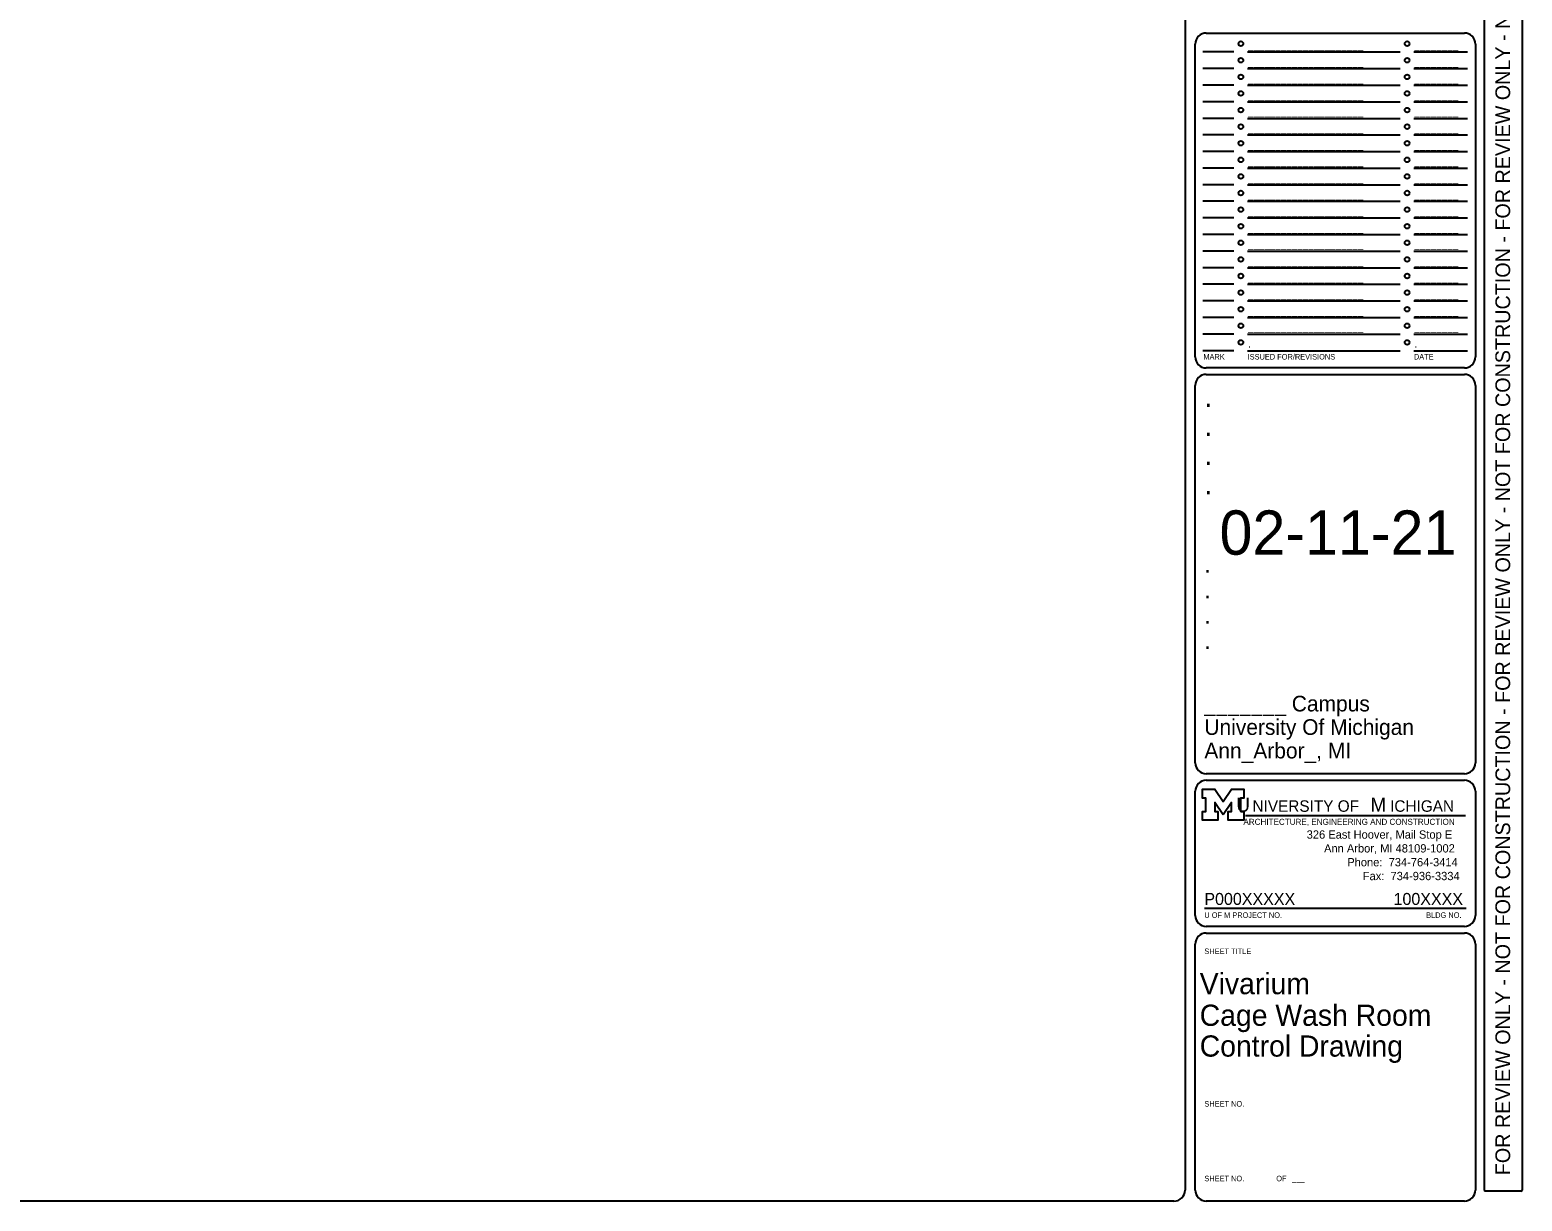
# Model space of a CAD drawing. Extents: x 0 to 567, y 1 to 184.
# Drawn here: x 432.3 to 567.1, y 1.7 to 107.6 of the extents above; entities that cross this region are included whole.
import ezdxf

# ---------------------------------------------------------------- set-up
doc = ezdxf.new("R2010")
doc.units = 0
for name, color, linetype in [('G-ANNO-CELL', 7, 'Continuous'), ('G-ANNO-LOGO', 7, 'Continuous'), ('G-ANNO-PROJ', 7, 'Continuous'), ('G-ANNO-TTLB', 7, 'Continuous'), ('G-TITL-TEXT', 7, 'Continuous')]:
    doc.layers.add(name, color=color, linetype=linetype)

msp = doc.modelspace()

# ---------------------------------------------------------------- linework, layer by layer
at = {"layer": 'G-ANNO-LOGO'}
for p, q in [((538.24, 38.17), (538.24, 38.96)), ((538.24, 38.96), (539.36, 38.96)), ((538.54, 38.17), (538.24, 38.17)), ((538.54, 36.95), (538.54, 38.17)), ((539.36, 38.96), (540.12, 37.86)), ((540.12, 37.86), (540.88, 38.96)), ((540.88, 38.96), (541.99, 38.96)), ((541.99, 38.17), (541.7, 38.17)), ((541.7, 38.17), (541.7, 36.98)), ((541.99, 38.96), (541.99, 38.17)), ((538.24, 36.16), (538.24, 36.95)), ((538.24, 36.95), (538.54, 36.95)), ((540.12, 36.66), (539.36, 37.76)), ((539.36, 37.76), (539.36, 36.95)), ((539.36, 36.95), (539.65, 36.95)), ((539.65, 36.95), (539.65, 36.16)), ((540.88, 37.76), (540.12, 36.66)), ((540.58, 36.16), (540.58, 36.95)), ((540.58, 36.95), (540.88, 36.95)), ((540.88, 36.95), (540.88, 37.76)), ((541.7, 36.98), (541.77, 36.95)), ((541.77, 36.95), (541.99, 36.95)), ((541.99, 36.95), (541.99, 36.16)), ((542.14, 36.59), (562.03, 36.59)), ((539.65, 36.16), (538.24, 36.16)), ((541.99, 36.16), (540.58, 36.16))]:
    msp.add_line(p, q, dxfattribs=at)
msp.add_lwpolyline([(540.12, 36.66), (539.36, 37.76), (539.36, 36.95), (539.65, 36.95), (539.65, 36.16), (538.24, 36.16), (538.24, 36.95), (538.54, 36.95), (538.54, 38.17), (538.24, 38.17), (538.24, 38.96), (539.36, 38.96), (540.12, 37.86), (540.88, 38.96), (541.99, 38.96), (541.99, 38.17), (541.7, 38.17), (541.7, 36.98), (541.77, 36.95), (541.99, 36.95), (541.99, 36.16), (540.58, 36.16), (540.58, 36.95), (540.88, 36.95), (540.88, 37.76)], close=True, dxfattribs=at)
at = {"layer": 'G-ANNO-TTLB'}
for p, q in [((541.08, 105.61), (538.29, 105.61)), ((542.33, 105.61), (556.11, 105.61)), ((557.36, 105.61), (562.2, 105.61)), ((541.08, 104.11), (538.29, 104.11)), ((542.33, 104.11), (556.11, 104.11)), ((557.36, 104.11), (562.2, 104.11)), ((541.08, 102.61), (538.29, 102.61)), ((542.33, 102.61), (556.11, 102.61)), ((557.36, 102.61), (562.2, 102.61)), ((541.08, 101.11), (538.29, 101.11)), ((542.33, 101.11), (556.11, 101.11)), ((557.36, 101.11), (562.2, 101.11)), ((541.08, 99.61), (538.29, 99.61)), ((542.33, 99.61), (556.11, 99.61)), ((557.36, 99.61), (562.2, 99.61)), ((541.08, 98.11), (538.29, 98.11)), ((542.33, 98.11), (556.11, 98.11)), ((557.36, 98.11), (562.2, 98.11)), ((541.08, 96.61), (538.29, 96.61)), ((542.33, 96.61), (556.11, 96.61)), ((557.36, 96.61), (562.2, 96.61)), ((541.08, 95.11), (538.29, 95.11)), ((542.33, 95.11), (556.11, 95.11)), ((557.36, 95.11), (562.2, 95.11)), ((541.08, 93.61), (538.29, 93.61)), ((542.33, 93.61), (556.11, 93.61)), ((557.36, 93.61), (562.2, 93.61)), ((541.08, 92.11), (538.29, 92.11)), ((542.33, 92.11), (556.11, 92.11)), ((557.36, 92.11), (562.2, 92.11)), ((541.08, 90.61), (538.29, 90.61)), ((542.33, 90.61), (556.11, 90.61)), ((557.36, 90.61), (562.2, 90.61)), ((541.08, 89.11), (538.29, 89.11)), ((542.33, 89.11), (556.11, 89.11)), ((557.36, 89.11), (562.2, 89.11)), ((541.08, 87.61), (538.29, 87.61)), ((542.33, 87.61), (556.11, 87.61)), ((557.36, 87.61), (562.2, 87.61)), ((541.08, 86.11), (538.29, 86.11)), ((542.33, 86.11), (556.11, 86.11)), ((557.36, 86.11), (562.2, 86.11)), ((541.08, 84.61), (538.29, 84.61)), ((542.33, 84.61), (556.11, 84.61)), ((557.36, 84.61), (562.2, 84.61)), ((541.08, 83.11), (538.29, 83.11)), ((542.33, 83.11), (556.11, 83.11)), ((557.36, 83.11), (562.2, 83.11)), ((541.08, 81.61), (538.29, 81.61)), ((542.33, 81.61), (556.11, 81.61)), ((557.36, 81.61), (562.2, 81.61)), ((541.08, 80.11), (538.29, 80.11)), ((542.33, 80.11), (556.11, 80.11)), ((557.36, 80.11), (562.2, 80.11)), ((541.08, 78.61), (538.29, 78.61)), ((542.33, 78.61), (556.11, 78.61)), ((557.36, 78.61), (562.2, 78.61)), ((562.09, 28.18), (538.42, 28.18))]:
    msp.add_line(p, q, dxfattribs=at)
for points in [[(536.67, 182.73), (536.67, 2.73)], [(563.73, 2.73), (563.73, 182.73)], [(567.15, 182.73), (567.15, 2.73)], [(538.59, 107.32), (561.92, 107.32)], [(537.59, 78.05), (537.59, 106.32)], [(562.92, 106.32), (562.92, 78.05)], [(561.92, 77.05), (538.59, 77.05)], [(538.59, 76.47), (561.92, 76.47)], [(537.59, 41.36), (537.59, 75.47)], [(562.92, 75.47), (562.92, 41.36)], [(561.92, 40.36), (538.59, 40.36)], [(538.59, 39.78), (561.92, 39.78)], [(537.59, 27.56), (537.59, 38.78)], [(562.92, 38.78), (562.92, 27.56)], [(561.92, 26.56), (538.59, 26.56)], [(538.59, 25.97), (561.92, 25.97)], [(537.59, 2.74), (537.59, 24.97)], [(562.92, 24.97), (562.92, 2.74)], [(535.67, 1.73), (291.92, 1.73)], [(561.92, 1.74), (538.59, 1.74)], [(567.06, 2.65), (563.81, 2.65)]]:
    msp.add_lwpolyline(points, dxfattribs=at)
for centre in [(541.72, 106.36), (556.75, 106.36), (541.72, 104.86), (556.75, 104.86), (541.72, 103.36), (556.75, 103.36), (541.72, 101.86), (556.75, 101.86), (541.72, 100.36), (556.75, 100.36), (541.72, 98.86), (556.75, 98.86), (541.72, 97.36), (556.75, 97.36), (541.72, 95.86), (556.75, 95.86), (541.72, 94.36), (556.75, 94.36), (541.72, 92.86), (556.75, 92.86), (541.72, 91.36), (556.75, 91.36), (541.72, 89.86), (556.75, 89.86), (541.72, 88.36), (556.75, 88.36), (541.72, 86.86), (556.75, 86.86), (541.72, 85.36), (556.75, 85.36), (541.72, 83.86), (556.75, 83.86), (541.72, 82.36), (556.75, 82.36), (541.72, 80.86), (556.75, 80.86), (541.72, 79.36), (556.75, 79.36)]:
    msp.add_circle(centre, 0.214, dxfattribs=at)
for centre, radius, start, end in [((538.59, 106.32), 1, 90.0001, 180.0001), ((561.92, 106.32), 1, 0.0001, 90.0001), ((538.59, 78.05), 1, 180, 270), ((561.92, 78.05), 1, 270, 360), ((538.59, 75.47), 1, 90, 180), ((561.92, 75.47), 1, 0, 90), ((538.59, 41.36), 1, 180, 270), ((561.92, 41.36), 1, 270, 0), ((538.59, 38.78), 1, 90, 180), ((561.92, 38.78), 1, 0, 90), ((538.59, 27.56), 1, 180, 270), ((561.92, 27.56), 1, 270, 360), ((538.59, 24.97), 1, 90, 180), ((561.92, 24.97), 1, 0, 90), ((535.67, 2.73), 1, 270, 360), ((538.59, 2.74), 1, 180, 270), ((561.92, 2.74), 1, 270, 360), ((563.81, 2.73), 0.0833, 180, 270.0001), ((567.06, 2.73), 0.0833, 270.0001, 360)]:
    msp.add_arc(centre, radius, start, end, dxfattribs=at)

# ---------------------------------------------------------------- texts
at = {"layer": 'G-ANNO-CELL'}
msp.add_text('FOR REVIEW ONLY - NOT FOR CONSTRUCTION - FOR REVIEW ONLY - NOT FOR CONSTRUCTION - FOR REVIEW ONLY - NOT FOR CONSTRUCTION - FOR REVIEW ONLY - NOT FOR CONSTRUCTION', height=1.33333, rotation=90, dxfattribs=at).set_placement((566.06, 4.08))
at = {"layer": 'G-ANNO-LOGO'}
for s, height, p in [('U', 1.28, (541.31, 36.93)), ('NIVERSITY OF', 1.0368, (542.77, 36.93)), ('M', 1.28, (553.43, 36.93)), ('ICHIGAN', 1.037, (555.21, 36.93)), ('ARCHITECTURE, ENGINEERING AND CONSTRUCTION', 0.5469, (541.95, 35.75)), ('326 East Hoover, Mail Stop E', 0.75, (547.67, 34.5)), ('Ann Arbor, MI 48109-1002', 0.75, (549.24, 33.25)), ('Phone:  734-764-3414', 0.75, (551.34, 32)), ('Fax:  734-936-3334', 0.75, (552.74, 30.75))]:
    msp.add_text(s, height=height, dxfattribs=at).set_placement(p)
at = {"layer": 'G-ANNO-PROJ'}
for s, height, p in [('_____________________', 0.6667, (542.37, 105.89)), ('________', 0.667, (557.4, 105.89)), ('_____________________', 0.6667, (542.37, 104.39)), ('________', 0.667, (557.4, 104.39)), ('_____________________', 0.6667, (542.37, 102.89)), ('________', 0.667, (557.4, 102.89)), ('_____________________', 0.6667, (542.37, 101.39)), ('________', 0.667, (557.4, 101.39)), ('_____________________', 0.6667, (542.37, 99.89)), ('________', 0.667, (557.4, 99.89)), ('_____________________', 0.6667, (542.37, 98.39)), ('________', 0.667, (557.4, 98.39)), ('_____________________', 0.6667, (542.37, 96.89)), ('________', 0.667, (557.4, 96.89)), ('_____________________', 0.6667, (542.37, 95.39)), ('________', 0.667, (557.4, 95.39)), ('_____________________', 0.6667, (542.37, 93.89)), ('________', 0.667, (557.4, 93.89)), ('_____________________', 0.6667, (542.37, 92.39)), ('________', 0.667, (557.4, 92.39)), ('_____________________', 0.6667, (542.37, 90.89)), ('________', 0.667, (557.4, 90.89)), ('_____________________', 0.6667, (542.37, 89.39)), ('________', 0.667, (557.4, 89.39)), ('_____________________', 0.6667, (542.37, 87.89)), ('________', 0.667, (557.4, 87.89)), ('_____________________', 0.6667, (542.37, 86.39)), ('________', 0.667, (557.4, 86.39)), ('_____________________', 0.6667, (542.37, 84.89)), ('________', 0.667, (557.4, 84.89)), ('_____________________', 0.6667, (542.37, 83.39)), ('________', 0.667, (557.4, 83.39)), ('_____________________', 0.6667, (542.37, 81.89)), ('________', 0.667, (557.4, 81.89)), ('_____________________', 0.6667, (542.37, 80.39)), ('________', 0.667, (557.4, 80.39)), ('.', 0.667, (542.37, 78.89)), ('.', 0.667, (557.4, 78.89)), ('.', 1.92, (538.42, 73.52)), ('.', 1.92, (538.42, 70.89)), ('.', 1.92, (538.42, 68.27)), ('.', 1.92, (538.42, 65.64)), ('.', 1.58, (538.42, 58.53)), ('.', 1.58, (538.42, 56.23)), ('.', 1.58, (538.42, 53.94)), ('.', 1.58, (538.42, 51.65)), ('_______ Campus', 1.4167, (538.42, 46)), ('University Of Michigan', 1.4167, (538.42, 43.88)), ('Ann_Arbor_, MI', 1.4167, (538.42, 41.75)), ('P000XXXXX', 1.083, (538.42, 28.51)), ('100XXXX', 1.083, (555.52, 28.51)), ('SHEET NO.', 0.5, (538.42, 3.53)), ('OF', 0.5, (544.92, 3.53)), ('___', 0.5, (546.35, 3.53))]:
    msp.add_text(s, height=height, dxfattribs=at).set_placement(p)
at = {"layer": 'G-ANNO-TTLB'}
for s, p in [('MARK', (538.33, 77.81)), ('ISSUED FOR/REVISIONS', (542.33, 77.81)), ('DATE', (557.36, 77.81)), ('U OF M PROJECT NO.', (538.42, 27.34)), ('BLDG NO.', (558.47, 27.34)), ('SHEET TITLE', (538.42, 24.07)), ('SHEET NO.', (538.42, 10.28))]:
    msp.add_text(s, height=0.5, dxfattribs=at).set_placement(p)
at = {"layer": 'G-TITL-TEXT'}
for s, height, p in [('02-11-21', 4, (539.79, 60.17)), ('Vivarium', 1.917, (538, 20.44)), ('Cage Wash Room', 1.9167, (538, 17.58)), ('Control Drawing', 1.9167, (538, 14.8))]:
    msp.add_text(s, height=height, dxfattribs=at).set_placement(p)

doc.saveas('drawing.dxf')
